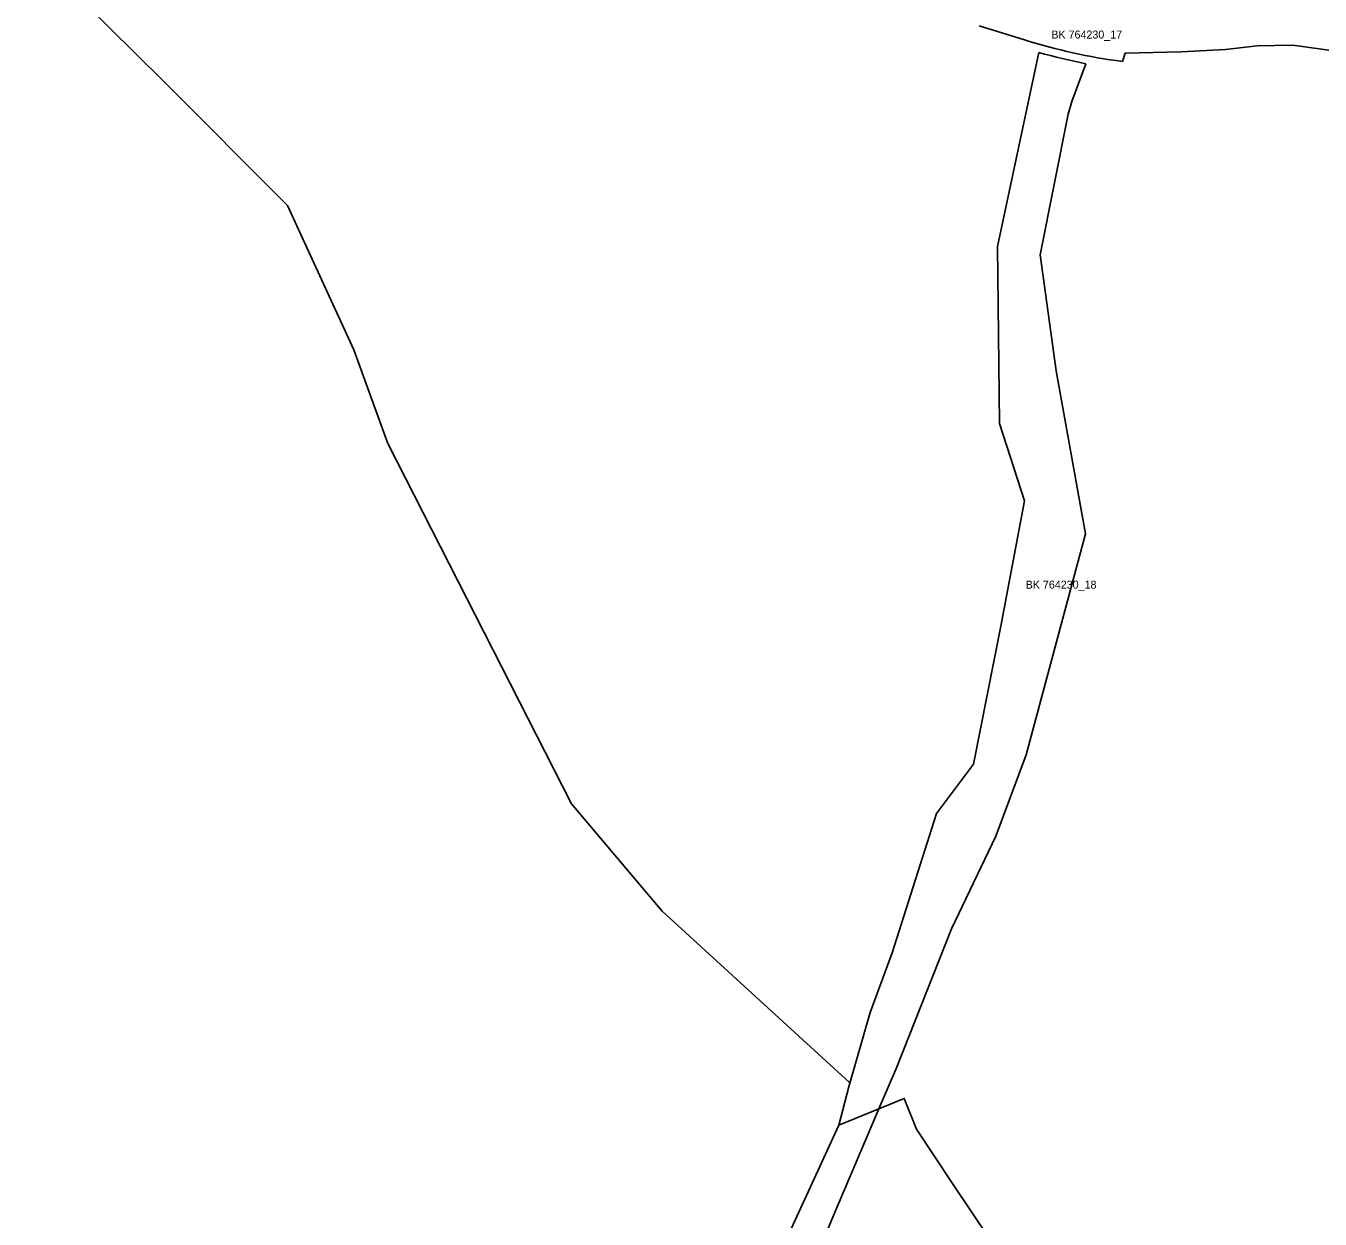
# Model space of a CAD drawing. Extents: x -521616 to -516782, y -1190061 to -1184927.
# Drawn here: x -518534 to -517887, y -1188489 to -1187893 of the extents above; entities that cross this region are included whole.
import ezdxf

# ---------------------------------------------------------------- set-up
doc = ezdxf.new("R2010")
doc.units = 0
for name, color, linetype in [('i_prvek_l_s', 7, 'Continuous'), ('LBC_n', 7, 'Continuous'), ('LBC_s', 7, 'Continuous'), ('LBK_s', 7, 'Continuous')]:
    doc.layers.add(name, color=color, linetype=linetype)

msp = doc.modelspace()

# ---------------------------------------------------------------- linework, layer by layer
at = {"layer": 'i_prvek_l_s'}
msp.add_lwpolyline([(-518122.21, -1188421.13), (-518215.84, -1188335.41), (-518261.14, -1188281.69), (-518352.92, -1188101.67), (-518369.92, -1188054.86), (-518403.1, -1187982.61), (-518465.07, -1187920.47), (-518533.9, -1187852.4)], dxfattribs=at)
at = {"layer": 'LBC_n'}
msp.add_lwpolyline([(-518107.55, -1188434.21), (-518094.86, -1188429.01), (-518088.83, -1188444.38), (-518071.02, -1188470.99), (-517981.98, -1188604), (-517899.19, -1188742.67), (-518042.67, -1188683.14), (-518186.15, -1188623.6), (-518130.29, -1188487.49)], close=True, dxfattribs=at)
at = {"layer": 'LBC_s'}
msp.add_lwpolyline([(-518178.05, -1188552.15), (-518127.51, -1188442.39), (-518107.55, -1188434.21), (-518130.29, -1188487.49), (-518186.15, -1188623.6)], dxfattribs=at)
at = {"layer": 'LBK_s'}
for points in [[(-518034.74, -1187899.9), (-518057.46, -1187892.84)], [(-517832.59, -1187911.97), (-517900.65, -1187902.56), (-517918.4, -1187902.87), (-517934.29, -1187904.57), (-517956.52, -1187905.8), (-517984.49, -1187906.53), (-517985.86, -1187910.67)], [(-518004.05, -1187911.74), (-518011.07, -1187930.61), (-518012.92, -1187936.94), (-518026.89, -1188007.23), (-518018.86, -1188065.26), (-518004.36, -1188146.74), (-518033.99, -1188257.24), (-518049.11, -1188297.98), (-518071.33, -1188344.28), (-518098.8, -1188413.72), (-518107.55, -1188434.21), (-518127.51, -1188442.39), (-518122.42, -1188422.6), (-518111.92, -1188386.02), (-518100.97, -1188356.24), (-518078.74, -1188286.64), (-518060.22, -1188261.94), (-518046.64, -1188192.96), (-518034.76, -1188130.3), (-518047.26, -1188091.57), (-518048.19, -1188003.14), (-518027.63, -1187906.16)]]:
    msp.add_lwpolyline(points, dxfattribs=at)
for radius, start, end in [(298, 252.75379, 262.38774), (302, 254.39436, 258.99307)]:
    msp.add_arc((-517946.39, -1187615.29), radius, start, end, dxfattribs=at)

# ---------------------------------------------------------------- texts
for s, p in [('BK 764230_17', (-518021.36, -1187899.18)), ('BK 764230_18', (-518034.19, -1188174.18))]:
    msp.add_text(s, height=4, dxfattribs=at).set_placement(p)

doc.saveas('drawing.dxf')
